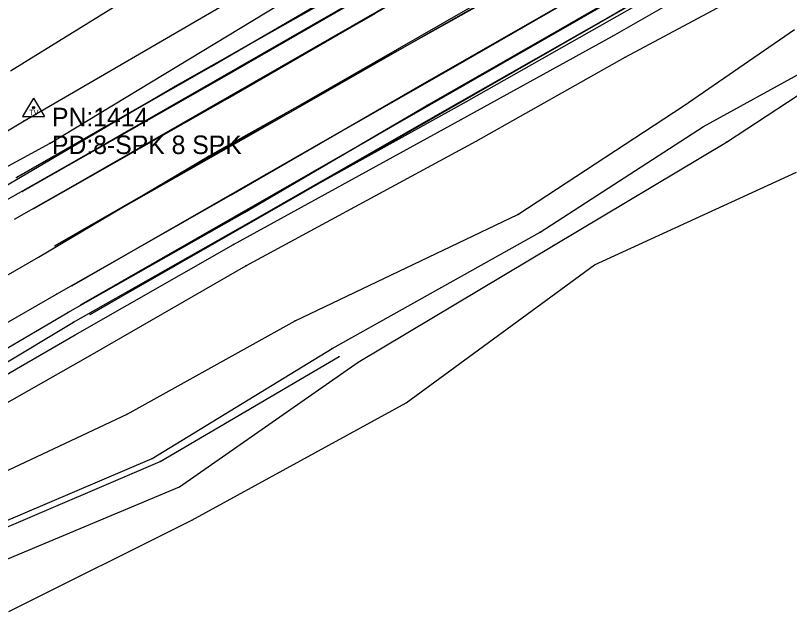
# Model space of a CAD drawing. Extents: x 1419505 to 1434054, y 1956910 to 1968644.
# Drawn here: x 1421697.6 to 1421906.9, y 1958082.6 to 1958243.6 of the extents above; entities that cross this region are included whole.
import ezdxf

# ---------------------------------------------------------------- set-up
doc = ezdxf.new("R2010")
doc.units = 0
for name, color, linetype in [('S_BREAKLINE', 7, 'Continuous'), ('S_DITCHLINE', 7, 'Continuous'), ('S_EDGE_PAVEMENT', 7, 'Continuous'), ('S_GRD_PT_SYM', 7, 'Continuous'), ('S_PAVEMENT_CROWN', 7, 'Continuous'), ('S_RDW_PT_SYM', 7, 'Continuous'), ('S_SECONDARY_CTL', 7, 'Continuous'), ('S_SECONDARY_CTL_ANNOT', 7, 'Continuous'), ('S_SHOULDER', 7, 'Continuous')]:
    doc.layers.add(name, color=color, linetype=linetype)

msp = doc.modelspace()

# ---------------------------------------------------------------- linework, layer by layer
at = {"layer": 'S_BREAKLINE'}
for p, q in [((1422234.7195, 1958507.1234), (1421697.9208, 1958199.8056)), ((1422256.1529, 1958471.0691), (1421717.7711, 1958162.8162)), ((1421696.2357, 1958228.6925), (1421783.0763, 1958282.2349)), ((1421858.4792, 1958243.4524), (1421905.5902, 1958271.2752)), ((1421699.952, 1958215.1896), (1421782.6453, 1958263.1957)), ((1421706.9714, 1958209.1252), (1421787.3476, 1958257.7703)), ((1421750.5502, 1958229.8155), (1421799.4204, 1958258.3784)), ((1421858.9662, 1958238.0111), (1421893.8825, 1958258.0443)), ((1421740.8066, 1958224.5522), (1421790.0898, 1958252.356)), ((1421862.4755, 1958232.3747), (1421897.9767, 1958251.4039)), ((1421819.5487, 1958220.4149), (1421865.6917, 1958246.4556)), ((1421811.1971, 1958216.5147), (1421858.4792, 1958243.4524)), ((1421878.1265, 1958219.1358), (1421908.1844, 1958239.8192)), ((1421818.1346, 1958215.5306), (1421858.9662, 1958238.0111)), ((1421822.1609, 1958209.6272), (1421862.4755, 1958232.3747)), ((1421697.9208, 1958199.8056), (1421750.5502, 1958229.8155)), ((1421883.6178, 1958213.5965), (1421914.0198, 1958230.3826)), ((1421692.7975, 1958196.2984), (1421740.8066, 1958224.5522)), ((1421769.9565, 1958192.8921), (1421819.5487, 1958220.4149)), ((1421833.3846, 1958189.8009), (1421878.1265, 1958219.1358)), ((1421761.1919, 1958187.8248), (1421811.1971, 1958216.5147)), ((1421598.9034, 1958154.4097), (1421699.952, 1958215.1896)), ((1421756.5596, 1958181.7554), (1421818.1346, 1958215.5306)), ((1421839.439, 1958185.1066), (1421883.6178, 1958213.5965)), ((1421759.8898, 1958176), (1421822.1609, 1958209.6272)), ((1421600.8836, 1958151.1174), (1421706.9714, 1958209.1252)), ((1421854.1559, 1958176.2071), (1421908.7594, 1958201.2967)), ((1421717.7711, 1958162.8162), (1421769.9565, 1958192.8921)), ((1421773.1997, 1958161.1201), (1421833.3846, 1958189.8009)), ((1421713.3048, 1958160.7661), (1421761.1919, 1958187.8248)), ((1421783.2203, 1958153.6786), (1421839.439, 1958185.1066)), ((1421713.7689, 1958157.3178), (1421756.5596, 1958181.7554)), ((1421803.1966, 1958138.9517), (1421854.1559, 1958176.2071)), ((1421717.8411, 1958151.7525), (1421759.8898, 1958176)), ((1421678.0445, 1958139.6687), (1421713.3048, 1958160.7661)), ((1421727.7668, 1958135.9475), (1421773.1997, 1958161.1201)), ((1421656.2781, 1958124.2587), (1421713.7689, 1958157.3178)), ((1421734.5962, 1958123.9707), (1421783.2203, 1958153.6786)), ((1421660.4324, 1958119.3134), (1421717.8411, 1958151.7525)), ((1421745.3329, 1958107.2626), (1421803.1966, 1958138.9517)), ((1421670.015, 1958108.6617), (1421727.7668, 1958135.9475)), ((1421679.4156, 1958100.4772), (1421734.5962, 1958123.9707)), ((1421695.7997, 1958082.591), (1421745.3329, 1958107.2626))]:
    msp.add_line(p, q, dxfattribs=at)
at = {"layer": 'S_DITCHLINE'}
for p, q in [((1421889.8312, 1958209.4182), (1421916.5319, 1958226.9663)), ((1421843.0372, 1958181.4944), (1421889.8312, 1958209.4182)), ((1421790.2838, 1958149.9304), (1421843.0372, 1958181.4944)), ((1421736.7203, 1958123.0916), (1421785.1315, 1958151.5025)), ((1421741.9597, 1958116.2332), (1421790.2838, 1958149.9304)), ((1421681.2658, 1958099.3861), (1421736.7203, 1958123.0916)), ((1421688.8222, 1958094.0388), (1421741.9597, 1958116.2332))]:
    msp.add_line(p, q, dxfattribs=at)
at = {"layer": 'S_EDGE_PAVEMENT'}
for p, q in [((1422239.4358, 1958499.3739), (1421702.5421, 1958191.435)), ((1422250.9195, 1958479.1606), (1421712.8678, 1958170.5937)), ((1421815.2854, 1958229.1945), (1421862.1364, 1958256.1602)), ((1421806.5868, 1958224.3822), (1421855.613, 1958252.494)), ((1421754.9145, 1958221.217), (1421804.7397, 1958249.9838)), ((1421744.7359, 1958215.4796), (1421794.8581, 1958244.1745)), ((1421765.3862, 1958200.7206), (1421815.2854, 1958229.1945)), ((1421755.9246, 1958195.1473), (1421806.5868, 1958224.3822)), ((1421702.5421, 1958191.435), (1421754.9145, 1958221.217)), ((1421697.3168, 1958188.5809), (1421744.7359, 1958215.4796)), ((1421712.8678, 1958170.5937), (1421765.3862, 1958200.7206)), ((1421708.6815, 1958168.3096), (1421755.9246, 1958195.1473)), ((1421672.4722, 1958147.6052), (1421708.6815, 1958168.3096))]:
    msp.add_line(p, q, dxfattribs=at)
at = {"layer": 'S_GRD_PT_SYM'}
for points in [[(1421858.4792, 1958243.4524), (1421858.4792, 1958243.5024), (1421858.4792, 1958243.4524), (1421858.4292, 1958243.4524), (1421858.4792, 1958243.4524), (1421858.4792, 1958243.4024), (1421858.4792, 1958243.4524), (1421858.5292, 1958243.4524)], [(1421858.9662, 1958238.0111), (1421858.9662, 1958238.0611), (1421858.9662, 1958238.0111), (1421858.9162, 1958238.0111), (1421858.9662, 1958238.0111), (1421858.9662, 1958237.9611), (1421858.9662, 1958238.0111), (1421859.0162, 1958238.0111)], [(1421862.4755, 1958232.3747), (1421862.4755, 1958232.4247), (1421862.4755, 1958232.3747), (1421862.4255, 1958232.3747), (1421862.4755, 1958232.3747), (1421862.4755, 1958232.3247), (1421862.4755, 1958232.3747), (1421862.5255, 1958232.3747)], [(1421750.5502, 1958229.8155), (1421750.5502, 1958229.8655), (1421750.5502, 1958229.8155), (1421750.5002, 1958229.8155), (1421750.5502, 1958229.8155), (1421750.5502, 1958229.7655), (1421750.5502, 1958229.8155), (1421750.6002, 1958229.8155)], [(1421740.8066, 1958224.5522), (1421740.8066, 1958224.6022), (1421740.8066, 1958224.5522), (1421740.7566, 1958224.5522), (1421740.8066, 1958224.5522), (1421740.8066, 1958224.5022), (1421740.8066, 1958224.5522), (1421740.8566, 1958224.5522)], [(1421819.5487, 1958220.4149), (1421819.5487, 1958220.4649), (1421819.5487, 1958220.4149), (1421819.4987, 1958220.4149), (1421819.5487, 1958220.4149), (1421819.5487, 1958220.3649), (1421819.5487, 1958220.4149), (1421819.5987, 1958220.4149)], [(1421878.1265, 1958219.1358), (1421878.1265, 1958219.1858), (1421878.1265, 1958219.1358), (1421878.0765, 1958219.1358), (1421878.1265, 1958219.1358), (1421878.1265, 1958219.0858), (1421878.1265, 1958219.1358), (1421878.1765, 1958219.1358)], [(1421811.1971, 1958216.5147), (1421811.1971, 1958216.5647), (1421811.1971, 1958216.5147), (1421811.1471, 1958216.5147), (1421811.1971, 1958216.5147), (1421811.1971, 1958216.4647), (1421811.1971, 1958216.5147), (1421811.2471, 1958216.5147)], [(1421699.952, 1958215.1896), (1421699.952, 1958215.2396), (1421699.952, 1958215.1896), (1421699.902, 1958215.1896), (1421699.952, 1958215.1896), (1421699.952, 1958215.1396), (1421699.952, 1958215.1896), (1421700.002, 1958215.1896)], [(1421818.1346, 1958215.5306), (1421818.1346, 1958215.5806), (1421818.1346, 1958215.5306), (1421818.0846, 1958215.5306), (1421818.1346, 1958215.5306), (1421818.1346, 1958215.4806), (1421818.1346, 1958215.5306), (1421818.1846, 1958215.5306)], [(1421883.6178, 1958213.5965), (1421883.6178, 1958213.6465), (1421883.6178, 1958213.5965), (1421883.5678, 1958213.5965), (1421883.6178, 1958213.5965), (1421883.6178, 1958213.5465), (1421883.6178, 1958213.5965), (1421883.6678, 1958213.5965)], [(1421822.1609, 1958209.6272), (1421822.1609, 1958209.6772), (1421822.1609, 1958209.6272), (1421822.1109, 1958209.6272), (1421822.1609, 1958209.6272), (1421822.1609, 1958209.5772), (1421822.1609, 1958209.6272), (1421822.2109, 1958209.6272)], [(1421706.9714, 1958209.1252), (1421706.9714, 1958209.1752), (1421706.9714, 1958209.1252), (1421706.9214, 1958209.1252), (1421706.9714, 1958209.1252), (1421706.9714, 1958209.0752), (1421706.9714, 1958209.1252), (1421707.0214, 1958209.1252)], [(1421889.8312, 1958209.4182), (1421889.8312, 1958209.4682), (1421889.8312, 1958209.4182), (1421889.7812, 1958209.4182), (1421889.8312, 1958209.4182), (1421889.8312, 1958209.3682), (1421889.8312, 1958209.4182), (1421889.8812, 1958209.4182)], [(1421697.9208, 1958199.8056), (1421697.9208, 1958199.8556), (1421697.9208, 1958199.8056), (1421697.8708, 1958199.8056), (1421697.9208, 1958199.8056), (1421697.9208, 1958199.7556), (1421697.9208, 1958199.8056), (1421697.9708, 1958199.8056)], [(1421769.9565, 1958192.8921), (1421769.9565, 1958192.9421), (1421769.9565, 1958192.8921), (1421769.9065, 1958192.8921), (1421769.9565, 1958192.8921), (1421769.9565, 1958192.8421), (1421769.9565, 1958192.8921), (1421770.0065, 1958192.8921)], [(1421833.3846, 1958189.8009), (1421833.3846, 1958189.8509), (1421833.3846, 1958189.8009), (1421833.3346, 1958189.8009), (1421833.3846, 1958189.8009), (1421833.3846, 1958189.7509), (1421833.3846, 1958189.8009), (1421833.4346, 1958189.8009)], [(1421761.1919, 1958187.8248), (1421761.1919, 1958187.8748), (1421761.1919, 1958187.8248), (1421761.1419, 1958187.8248), (1421761.1919, 1958187.8248), (1421761.1919, 1958187.7748), (1421761.1919, 1958187.8248), (1421761.2419, 1958187.8248)], [(1421839.439, 1958185.1066), (1421839.439, 1958185.1566), (1421839.439, 1958185.1066), (1421839.389, 1958185.1066), (1421839.439, 1958185.1066), (1421839.439, 1958185.0566), (1421839.439, 1958185.1066), (1421839.489, 1958185.1066)], [(1421756.5596, 1958181.7554), (1421756.5596, 1958181.8054), (1421756.5596, 1958181.7554), (1421756.5096, 1958181.7554), (1421756.5596, 1958181.7554), (1421756.5596, 1958181.7054), (1421756.5596, 1958181.7554), (1421756.6096, 1958181.7554)], [(1421843.0372, 1958181.4944), (1421843.0372, 1958181.5444), (1421843.0372, 1958181.4944), (1421842.9872, 1958181.4944), (1421843.0372, 1958181.4944), (1421843.0372, 1958181.4444), (1421843.0372, 1958181.4944), (1421843.0872, 1958181.4944)], [(1421759.8898, 1958176), (1421759.8898, 1958176.05), (1421759.8898, 1958176), (1421759.8398, 1958176), (1421759.8898, 1958176), (1421759.8898, 1958175.95), (1421759.8898, 1958176), (1421759.9398, 1958176)], [(1421854.1559, 1958176.2071), (1421854.1559, 1958176.2571), (1421854.1559, 1958176.2071), (1421854.1059, 1958176.2071), (1421854.1559, 1958176.2071), (1421854.1559, 1958176.1571), (1421854.1559, 1958176.2071), (1421854.2059, 1958176.2071)], [(1421717.7711, 1958162.8162), (1421717.7711, 1958162.8662), (1421717.7711, 1958162.8162), (1421717.7211, 1958162.8162), (1421717.7711, 1958162.8162), (1421717.7711, 1958162.7662), (1421717.7711, 1958162.8162), (1421717.8211, 1958162.8162)], [(1421713.3048, 1958160.7661), (1421713.3048, 1958160.8161), (1421713.3048, 1958160.7661), (1421713.2548, 1958160.7661), (1421713.3048, 1958160.7661), (1421713.3048, 1958160.7161), (1421713.3048, 1958160.7661), (1421713.3548, 1958160.7661)], [(1421773.1997, 1958161.1201), (1421773.1997, 1958161.1701), (1421773.1997, 1958161.1201), (1421773.1497, 1958161.1201), (1421773.1997, 1958161.1201), (1421773.1997, 1958161.0701), (1421773.1997, 1958161.1201), (1421773.2497, 1958161.1201)], [(1421713.7689, 1958157.3178), (1421713.7689, 1958157.3678), (1421713.7689, 1958157.3178), (1421713.7189, 1958157.3178), (1421713.7689, 1958157.3178), (1421713.7689, 1958157.2678), (1421713.7689, 1958157.3178), (1421713.8189, 1958157.3178)], [(1421783.2203, 1958153.6786), (1421783.2203, 1958153.7286), (1421783.2203, 1958153.6786), (1421783.1703, 1958153.6786), (1421783.2203, 1958153.6786), (1421783.2203, 1958153.6286), (1421783.2203, 1958153.6786), (1421783.2703, 1958153.6786)], [(1421717.8411, 1958151.7525), (1421717.8411, 1958151.8025), (1421717.8411, 1958151.7525), (1421717.7911, 1958151.7525), (1421717.8411, 1958151.7525), (1421717.8411, 1958151.7025), (1421717.8411, 1958151.7525), (1421717.8911, 1958151.7525)], [(1421785.1315, 1958151.5025), (1421785.1315, 1958151.5525), (1421785.1315, 1958151.5025), (1421785.0815, 1958151.5025), (1421785.1315, 1958151.5025), (1421785.1315, 1958151.4525), (1421785.1315, 1958151.5025), (1421785.1815, 1958151.5025)], [(1421790.2838, 1958149.9304), (1421790.2838, 1958149.9804), (1421790.2838, 1958149.9304), (1421790.2338, 1958149.9304), (1421790.2838, 1958149.9304), (1421790.2838, 1958149.8804), (1421790.2838, 1958149.9304), (1421790.3338, 1958149.9304)], [(1421803.1966, 1958138.9517), (1421803.1966, 1958139.0017), (1421803.1966, 1958138.9517), (1421803.1466, 1958138.9517), (1421803.1966, 1958138.9517), (1421803.1966, 1958138.9017), (1421803.1966, 1958138.9517), (1421803.2466, 1958138.9517)], [(1421727.7668, 1958135.9475), (1421727.7668, 1958135.9975), (1421727.7668, 1958135.9475), (1421727.7168, 1958135.9475), (1421727.7668, 1958135.9475), (1421727.7668, 1958135.8975), (1421727.7668, 1958135.9475), (1421727.8168, 1958135.9475)], [(1421734.5962, 1958123.9707), (1421734.5962, 1958124.0207), (1421734.5962, 1958123.9707), (1421734.5462, 1958123.9707), (1421734.5962, 1958123.9707), (1421734.5962, 1958123.9207), (1421734.5962, 1958123.9707), (1421734.6462, 1958123.9707)], [(1421736.7203, 1958123.0916), (1421736.7203, 1958123.1416), (1421736.7203, 1958123.0916), (1421736.6703, 1958123.0916), (1421736.7203, 1958123.0916), (1421736.7203, 1958123.0416), (1421736.7203, 1958123.0916), (1421736.7703, 1958123.0916)], [(1421741.9597, 1958116.2332), (1421741.9597, 1958116.2832), (1421741.9597, 1958116.2332), (1421741.9097, 1958116.2332), (1421741.9597, 1958116.2332), (1421741.9597, 1958116.1832), (1421741.9597, 1958116.2332), (1421742.0097, 1958116.2332)], [(1421745.3329, 1958107.2626), (1421745.3329, 1958107.3126), (1421745.3329, 1958107.2626), (1421745.2829, 1958107.2626), (1421745.3329, 1958107.2626), (1421745.3329, 1958107.2126), (1421745.3329, 1958107.2626), (1421745.3829, 1958107.2626)]]:
    msp.add_lwpolyline(points, dxfattribs=at)
at = {"layer": 'S_PAVEMENT_CROWN'}
for p, q in [((1422245.2512, 1958489.5463), (1421708.2975, 1958181.3584)), ((1421809.9191, 1958239.2271), (1421857.7452, 1958266.3619)), ((1421801.1815, 1958234.1998), (1421850.4787, 1958262.1086)), ((1421759.2218, 1958210.2673), (1421809.9191, 1958239.2271)), ((1421750.0142, 1958205.73), (1421801.1815, 1958234.1998)), ((1421708.2975, 1958181.3584), (1421759.2218, 1958210.2673)), ((1421703.8482, 1958178.2972), (1421750.0142, 1958205.73)), ((1421666.6268, 1958156.9468), (1421703.8482, 1958178.2972))]:
    msp.add_line(p, q, dxfattribs=at)
at = {"layer": 'S_RDW_PT_SYM'}
for points in [[(1421809.9191, 1958239.2271), (1421809.9191, 1958239.2771), (1421809.9191, 1958239.2271), (1421809.8691, 1958239.2271), (1421809.9191, 1958239.2271), (1421809.9191, 1958239.1771), (1421809.9191, 1958239.2271), (1421809.9691, 1958239.2271)], [(1421801.1815, 1958234.1998), (1421801.1815, 1958234.2498), (1421801.1815, 1958234.1998), (1421801.1315, 1958234.1998), (1421801.1815, 1958234.1998), (1421801.1815, 1958234.1498), (1421801.1815, 1958234.1998), (1421801.2315, 1958234.1998)], [(1421815.2854, 1958229.1945), (1421815.2854, 1958229.2445), (1421815.2854, 1958229.1945), (1421815.2354, 1958229.1945), (1421815.2854, 1958229.1945), (1421815.2854, 1958229.1445), (1421815.2854, 1958229.1945), (1421815.3354, 1958229.1945)], [(1421752.8404, 1958226.3783), (1421752.8404, 1958226.4283), (1421752.8404, 1958226.3783), (1421752.7904, 1958226.3783), (1421752.8404, 1958226.3783), (1421752.8404, 1958226.3283), (1421752.8404, 1958226.3783), (1421752.8904, 1958226.3783)], [(1421806.5868, 1958224.3822), (1421806.5868, 1958224.4322), (1421806.5868, 1958224.3822), (1421806.5368, 1958224.3822), (1421806.5868, 1958224.3822), (1421806.5868, 1958224.3322), (1421806.5868, 1958224.3822), (1421806.6368, 1958224.3822)], [(1421817.8396, 1958224.3712), (1421817.8396, 1958224.4212), (1421817.8396, 1958224.3712), (1421817.7896, 1958224.3712), (1421817.8396, 1958224.3712), (1421817.8396, 1958224.3212), (1421817.8396, 1958224.3712), (1421817.8896, 1958224.3712)], [(1421742.6677, 1958220.7389), (1421742.6677, 1958220.7889), (1421742.6677, 1958220.7389), (1421742.6177, 1958220.7389), (1421742.6677, 1958220.7389), (1421742.6677, 1958220.6889), (1421742.6677, 1958220.7389), (1421742.7177, 1958220.7389)], [(1421754.9145, 1958221.217), (1421754.9145, 1958221.267), (1421754.9145, 1958221.217), (1421754.8645, 1958221.217), (1421754.9145, 1958221.217), (1421754.9145, 1958221.167), (1421754.9145, 1958221.217), (1421754.9645, 1958221.217)], [(1421808.811, 1958219.2648), (1421808.811, 1958219.3148), (1421808.811, 1958219.2648), (1421808.761, 1958219.2648), (1421808.811, 1958219.2648), (1421808.811, 1958219.2148), (1421808.811, 1958219.2648), (1421808.861, 1958219.2648)], [(1421744.7359, 1958215.4796), (1421744.7359, 1958215.5296), (1421744.7359, 1958215.4796), (1421744.6859, 1958215.4796), (1421744.7359, 1958215.4796), (1421744.7359, 1958215.4296), (1421744.7359, 1958215.4796), (1421744.7859, 1958215.4796)], [(1421759.2218, 1958210.2673), (1421759.2218, 1958210.3173), (1421759.2218, 1958210.2673), (1421759.1718, 1958210.2673), (1421759.2218, 1958210.2673), (1421759.2218, 1958210.2173), (1421759.2218, 1958210.2673), (1421759.2718, 1958210.2673)], [(1421750.0142, 1958205.73), (1421750.0142, 1958205.78), (1421750.0142, 1958205.73), (1421749.9642, 1958205.73), (1421750.0142, 1958205.73), (1421750.0142, 1958205.68), (1421750.0142, 1958205.73), (1421750.0642, 1958205.73)], [(1421765.3862, 1958200.7206), (1421765.3862, 1958200.7706), (1421765.3862, 1958200.7206), (1421765.3362, 1958200.7206), (1421765.3862, 1958200.7206), (1421765.3862, 1958200.6706), (1421765.3862, 1958200.7206), (1421765.4362, 1958200.7206)], [(1421699.4589, 1958196.0923), (1421699.4589, 1958196.1423), (1421699.4589, 1958196.0923), (1421699.4089, 1958196.0923), (1421699.4589, 1958196.0923), (1421699.4589, 1958196.0423), (1421699.4589, 1958196.0923), (1421699.5089, 1958196.0923)], [(1421755.9246, 1958195.1473), (1421755.9246, 1958195.1973), (1421755.9246, 1958195.1473), (1421755.8746, 1958195.1473), (1421755.9246, 1958195.1473), (1421755.9246, 1958195.0973), (1421755.9246, 1958195.1473), (1421755.9746, 1958195.1473)], [(1421768.2214, 1958195.6193), (1421768.2214, 1958195.6693), (1421768.2214, 1958195.6193), (1421768.1714, 1958195.6193), (1421768.2214, 1958195.6193), (1421768.2214, 1958195.5693), (1421768.2214, 1958195.6193), (1421768.2714, 1958195.6193)], [(1421702.5421, 1958191.435), (1421702.5421, 1958191.485), (1421702.5421, 1958191.435), (1421702.4921, 1958191.435), (1421702.5421, 1958191.435), (1421702.5421, 1958191.385), (1421702.5421, 1958191.435), (1421702.5921, 1958191.435)], [(1421759.5648, 1958190.383), (1421759.5648, 1958190.433), (1421759.5648, 1958190.383), (1421759.5148, 1958190.383), (1421759.5648, 1958190.383), (1421759.5648, 1958190.333), (1421759.5648, 1958190.383), (1421759.6148, 1958190.383)], [(1421708.2975, 1958181.3584), (1421708.2975, 1958181.4084), (1421708.2975, 1958181.3584), (1421708.2475, 1958181.3584), (1421708.2975, 1958181.3584), (1421708.2975, 1958181.3084), (1421708.2975, 1958181.3584), (1421708.3475, 1958181.3584)], [(1421703.8482, 1958178.2972), (1421703.8482, 1958178.3472), (1421703.8482, 1958178.2972), (1421703.7982, 1958178.2972), (1421703.8482, 1958178.2972), (1421703.8482, 1958178.2472), (1421703.8482, 1958178.2972), (1421703.8982, 1958178.2972)], [(1421712.8678, 1958170.5937), (1421712.8678, 1958170.6437), (1421712.8678, 1958170.5937), (1421712.8178, 1958170.5937), (1421712.8678, 1958170.5937), (1421712.8678, 1958170.5437), (1421712.8678, 1958170.5937), (1421712.9178, 1958170.5937)], [(1421708.6815, 1958168.3096), (1421708.6815, 1958168.3596), (1421708.6815, 1958168.3096), (1421708.6315, 1958168.3096), (1421708.6815, 1958168.3096), (1421708.6815, 1958168.2596), (1421708.6815, 1958168.3096), (1421708.7315, 1958168.3096)], [(1421715.306, 1958165.4004), (1421715.306, 1958165.4504), (1421715.306, 1958165.4004), (1421715.256, 1958165.4004), (1421715.306, 1958165.4004), (1421715.306, 1958165.3504), (1421715.306, 1958165.4004), (1421715.356, 1958165.4004)], [(1421711.7507, 1958163.3702), (1421711.7507, 1958163.4202), (1421711.7507, 1958163.3702), (1421711.7007, 1958163.3702), (1421711.7507, 1958163.3702), (1421711.7507, 1958163.3202), (1421711.7507, 1958163.3702), (1421711.8007, 1958163.3702)]]:
    msp.add_lwpolyline(points, dxfattribs=at)
at = {"layer": 'S_SECONDARY_CTL'}
for p, q in [((1421702.4951, 1958221.2859), (1421699.4851, 1958216.332)), ((1421702.4951, 1958221.2859), (1421705.4424, 1958216.332)), ((1421699.4851, 1958216.332), (1421705.4424, 1958216.332))]:
    msp.add_line(p, q, dxfattribs=at)
for radius in [0.3111, 0.1827, 0.1033]:
    msp.add_circle((1421702.4951, 1958218.6758), radius, dxfattribs=at)
at = {"layer": 'S_SHOULDER'}
for p, q in [((1422236.8876, 1958504.0772), (1421699.4589, 1958196.0923)), ((1422254.1918, 1958474.1573), (1421715.306, 1958165.4004)), ((1421752.8404, 1958226.3783), (1421801.5675, 1958254.4861)), ((1421817.8396, 1958224.3712), (1421864.5826, 1958251.2879)), ((1421742.6677, 1958220.7389), (1421791.6119, 1958248.9488)), ((1421808.811, 1958219.2648), (1421857.6421, 1958247.1836)), ((1421699.4589, 1958196.0923), (1421752.8404, 1958226.3783)), ((1421768.2214, 1958195.6193), (1421817.8396, 1958224.3712)), ((1421694.5006, 1958193.3152), (1421742.6677, 1958220.7389)), ((1421759.5648, 1958190.383), (1421808.811, 1958219.2648)), ((1421715.306, 1958165.4004), (1421768.2214, 1958195.6193)), ((1421711.7507, 1958163.3702), (1421759.5648, 1958190.383)), ((1421675.4774, 1958142.0249), (1421711.7507, 1958163.3702))]:
    msp.add_line(p, q, dxfattribs=at)

# ---------------------------------------------------------------- texts
at = {"layer": 'S_SECONDARY_CTL'}
msp.add_text('TV', height=1.5, rotation=360, dxfattribs=at).set_placement((1421701.2904, 1958216.6645))
at = {"layer": 'S_SECONDARY_CTL_ANNOT'}
for s, p in [('PN:1414', (1421707.4951, 1958213.6758)), ('PD:8-SPK 8 SPK', (1421707.4951, 1958206.1758))]:
    msp.add_text(s, height=5, dxfattribs=at).set_placement(p)

doc.saveas('drawing.dxf')
